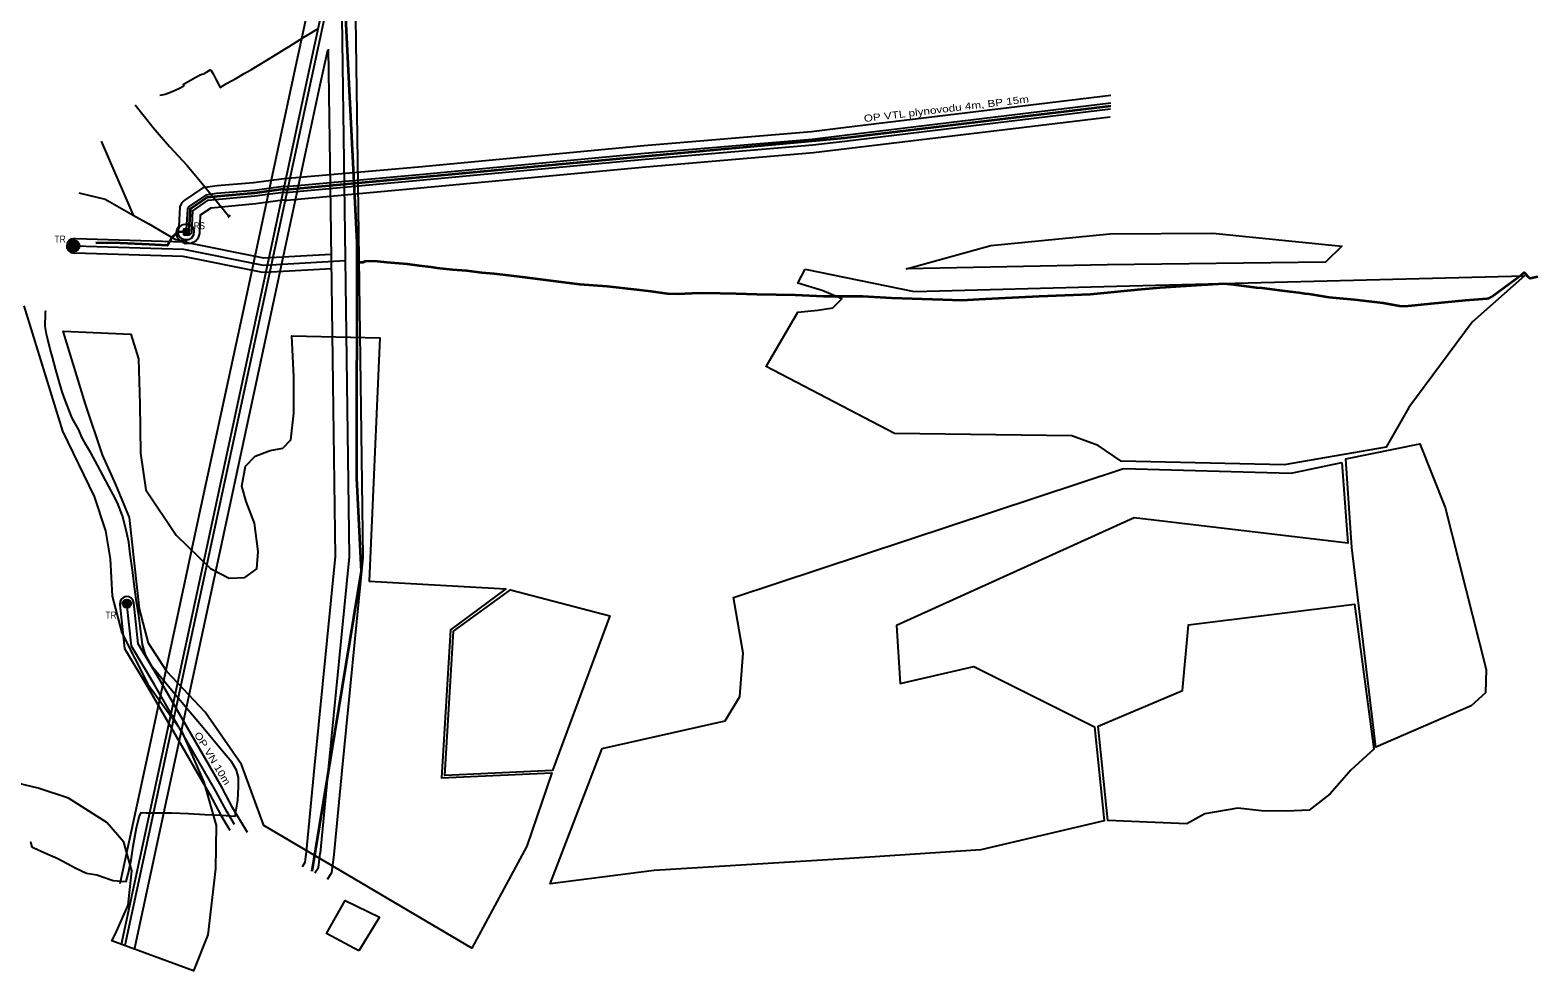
# Model space of a CAD drawing. Extents: x -589836 to -586543, y -1119607 to -1116793.
# Drawn here: x -588693 to -586543, y -1119607 to -1118266 of the extents above; entities that cross this region are included whole.
import ezdxf

# ---------------------------------------------------------------- set-up
doc = ezdxf.new("R2010")
doc.units = 0
doc.header["$LTSCALE"] = 4
for name, color, linetype, lineweight in [('21', 7, 'Continuous', 25), ('22', 7, 'Continuous', 25), ('25', 7, 'Continuous', 25), ('26', 7, 'Continuous', 25), ('29', 7, 'Continuous', 25), ('31', 7, 'Continuous', 25), ('45', 7, 'Continuous', 25), ('49', 7, 'Continuous', 25), ('51', 7, 'Continuous', 35), ('53', 7, 'Continuous', 35), ('57', 7, 'Continuous', 25), ('58', 7, 'Continuous', 25), ('59', 7, 'Continuous', 25)]:
    doc.layers.add(name, color=color, linetype=linetype, lineweight=lineweight)

msp = doc.modelspace()

# ---------------------------------------------------------------- hatches: boundary and pattern name
at = {"layer": '29'}
for points in [[(-588623.126, -1118573.346, 1), (-588639.226, -1118573.346, 1)], [(-588549.665, -1119083.315, 1), (-588561.739, -1119083.315, 1)]]:
    msp.add_hatch(color=256, dxfattribs=at).paths.add_polyline_path(points)
at = {"layer": '59'}
msp.add_hatch(color=256, dxfattribs=at).paths.add_polyline_path([(-588474.962, -1118557.448), (-588466.962, -1118557.448), (-588466.962, -1118549.448), (-588474.962, -1118549.448)])

# ---------------------------------------------------------------- linework, layer by layer
at = {"layer": '21'}
for points in [[(-587457.391, -1116891.203), (-587467.495, -1116906.128), (-587678.431, -1117217.658), (-587869.495, -1117499.964), (-588057.978, -1117778.27), (-588234.704, -1118039.283), (-588299.251, -1118339.426), (-588366.538, -1118652.377), (-588434.124, -1118966.627), (-588505.333, -1119297.805), (-588563.874, -1119569.266)], [(-588222.732, -1117991.024), (-588240.555, -1118139.541), (-588249.547, -1118212.86), (-588245.083, -1118520.625), (-588241.831, -1118769.889), (-588238.396, -1119016.784), (-588268.401, -1119319.835), (-588280.072, -1119439.07)], [(-588629.251, -1118573.381), (-588474.779, -1118578.006), (-588361.209, -1118600.912), (-588350.308, -1118600.364), (-588244.393, -1118594.251)], [(-588401.912, -1119398.276), (-588413.054, -1119379.796), (-588428.514, -1119350.663), (-588516.693, -1119198.167), (-588549.117, -1119143.934), (-588555.689, -1119083.288)], [(-588287.339, -1119467.122), (-588282.404, -1119459.508), (-588280.072, -1119439.07)]]:
    msp.add_lwpolyline(points, dxfattribs=at)
at = {"layer": '22'}
for points in [[(-588260.167, -1119441.018), (-588248.497, -1119321.794), (-588218.382, -1119017.633), (-588221.833, -1118769.619), (-588225.085, -1118520.35), (-588229.529, -1118213.937), (-588220.701, -1118141.95), (-588202.874, -1117993.407)], [(-588246.811, -1118021.492), (-588253.441, -1118031.284), (-588318.804, -1118335.221), (-588386.091, -1118648.172), (-588453.677, -1118962.422), (-588524.885, -1119293.595), (-588565.713, -1119482.918)], [(-588544.923, -1119576.263), (-588485.781, -1119302.015), (-588414.571, -1118970.832), (-588346.985, -1118656.582), (-588279.698, -1118343.631), (-588269.092, -1118294.315)], [(-588268.388, -1118292.891), (-588265.081, -1118520.9), (-588261.829, -1118770.159), (-588258.41, -1119015.935), (-588288.305, -1119317.876), (-588299.977, -1119437.122)], [(-588264.24, -1118585.38), (-588350.847, -1118590.378), (-588360.46, -1118590.862), (-588473.633, -1118568.036), (-588628.952, -1118563.385)], [(-588629.55, -1118583.377), (-588475.925, -1118587.976), (-588361.958, -1118610.962), (-588349.769, -1118610.35), (-588263.979, -1118605.398)], [(-588565.631, -1119084.365), (-588558.823, -1119147.187), (-588525.313, -1119203.236), (-588437.262, -1119355.511), (-588421.759, -1119384.725), (-588408.86, -1119406.12)], [(-588383.35, -1119409.696), (-588404.349, -1119374.867), (-588419.766, -1119345.815), (-588508.073, -1119193.098), (-588539.411, -1119140.681), (-588545.747, -1119082.211)], [(-588299.943, -1119436.803), (-588301.742, -1119452.573), (-588305.56, -1119458.464)], [(-588269.457, -1119476.304), (-588263.066, -1119466.443), (-588260.201, -1119441.337)]]:
    msp.add_lwpolyline(points, dxfattribs=at)
for centre, radius, start, end in [((-588631.176, -1118573.346), 10.206, 77.41396, 279.20742), ((-588555.689, -1119083.288), 10, 6.18264, 186.18264)]:
    msp.add_arc(centre, radius, start, end, dxfattribs=at)
at = {"layer": '25'}
msp.add_lwpolyline([(-587453.687, -1116893.154), (-588229.609, -1118041.457), (-588558.571, -1119570.952)], dxfattribs=at)
at = {"layer": '26'}
for points in [[(-588448.66, -1118328.38), (-588445.41, -1118327.83), (-588442.05, -1118325.59), (-588436.95, -1118322.56), (-588435.86, -1118323.02), (-588432.61, -1118327.98), (-588431.14, -1118330.67), (-588428.92, -1118335.66), (-588422.7, -1118347.43), (-588413.31, -1118341.77), (-588399.43, -1118333.99), (-588388.15, -1118327.5), (-588377.79, -1118321.88), (-588349.81, -1118304.9), (-588341.2, -1118299.4), (-588329.9, -1118292.46), (-588324.2, -1118289.02), (-588318.96, -1118285.98), (-588303.08, -1118275.73), (-588297.36, -1118272.24), (-588284.44, -1118264.16)], [(-588491.16, -1118353.17), (-588481.55, -1118348.82), (-588474.38, -1118345.04), (-588474.24, -1118344.52), (-588474.23, -1118344.19), (-588474.86, -1118342.87), (-588474.07, -1118342.27), (-588461.38, -1118335.31), (-588451.86, -1118329.92), (-588448.66, -1118328.38)], [(-588508.51, -1118358.49), (-588505.14, -1118358.08), (-588500.92, -1118356.95), (-588491.16, -1118353.17)], [(-588693.26, -1119423.62), (-588692.8, -1119423.53), (-588691.3, -1119430.3), (-588689.26, -1119431.22), (-588683.17, -1119433.96), (-588668.31, -1119440.47), (-588654.85, -1119446.03), (-588646.74, -1119450.41), (-588628.21, -1119460.68), (-588613.09, -1119467.49), (-588598.64, -1119470.05), (-588575, -1119478), (-588556.66, -1119479.54), (-588553.91, -1119469.06), (-588549.35, -1119449.22), (-588546.41, -1119429.3), (-588541.75, -1119402.8), (-588537.92, -1119387.07), (-588535.18, -1119381.34), (-588528.69, -1119381.52), (-588516.84, -1119381.44), (-588492.12, -1119381.56), (-588467.64, -1119382.47), (-588444.55, -1119383.85), (-588420.73, -1119384.88), (-588400.93, -1119386.31), (-588397.47, -1119363.42), (-588396.44, -1119344.44), (-588396.61, -1119331.22), (-588399.18, -1119320.84), (-588405.89, -1119309.42), (-588419.19, -1119293.72), (-588444.46, -1119263.25), (-588449.18, -1119257.64), (-588467.15, -1119236.1), (-588491.89, -1119206.56), (-588519.16, -1119173.98), (-588528.89, -1119156.11), (-588533.11, -1119141.77), (-588535.39, -1119126.68), (-588538.71, -1119100.28), (-588541.72, -1119080.76), (-588545.08, -1119055.45), (-588547.09, -1119039.14), (-588549.46, -1119022.37), (-588550.92, -1119013.06), (-588553, -1118995.85), (-588556.5, -1118978.44), (-588561.81, -1118958.38), (-588568.96, -1118939.87), (-588574.89, -1118927.96), (-588581.25, -1118916.23), (-588589.8, -1118900.37), (-588597.3, -1118886.03), (-588607.11, -1118868.2), (-588613.89, -1118856.25), (-588619.87, -1118846.11), (-588624.08, -1118835.53), (-588633.35, -1118818.97), (-588637.94, -1118808.18), (-588643.62, -1118793.34), (-588647.63, -1118781.51), (-588653.31, -1118763.48), (-588656.69, -1118750.17), (-588661.53, -1118732.2), (-588665.17, -1118720.57), (-588668.5, -1118706.99), (-588670.29, -1118699.03), (-588671.97, -1118687.72), (-588671.94, -1118682.03), (-588671.716, -1118675.944), (-588671.561, -1118671.707), (-588671.42, -1118667.88), (-588671.24, -1118666.44), (-588670.85, -1118666.42)]]:
    msp.add_lwpolyline(points, dxfattribs=at)
at = {"layer": '29'}
for centre, radius in [((-588631.176, -1118573.346), 8.05), ((-588555.702, -1119083.315), 6.037)]:
    msp.add_circle(centre, radius, dxfattribs=at)
at = {"layer": '31'}
for p, q in [((-588543.76, -1118372.1), (-588517.95, -1118404.41)), ((-588517.95, -1118404.41), (-588494.8, -1118431.51)), ((-588494.8, -1118431.51), (-588469.66, -1118458.68)), ((-588469.66, -1118458.68), (-588445.93, -1118487.06)), ((-588445.93, -1118487.06), (-588409.96, -1118530.99)), ((-588624.18, -1118497.82), (-588586.59, -1118506.54)), ((-588410.926, -1118531.781), (-588410.219, -1118532.646)), ((-588524.46, -1118542.09), (-588486.06, -1118564.06)), ((-588486.06, -1118564.06), (-588471.01, -1118566.77)), ((-588471.231, -1118568), (-588470.131, -1118568.198))]:
    msp.add_line(p, q, dxfattribs=at)
for points in [[(-588592.18, -1118424.23), (-588581.697, -1118448.396), (-588546.478, -1118529.471)], [(-588586.59, -1118506.54), (-588546.478, -1118529.471), (-588524.46, -1118542.09)], [(-588410.926, -1118531.781), (-588409.96, -1118530.99), (-588408.993, -1118530.198), (-588408.285, -1118531.063)], [(-588471.231, -1118568), (-588471.01, -1118566.77), (-588470.788, -1118565.541), (-588469.689, -1118565.739)]]:
    msp.add_lwpolyline(points, dxfattribs=at)
at = {"layer": '45'}
for points in [[(-587157.878, -1118600.13), (-587443.92, -1118606.155), (-587323.481, -1118572.59), (-587154.007, -1118556.238), (-587006.812, -1118555.143), (-586822.785, -1118573.611), (-586846.458, -1118596.688)], [(-587588.359, -1118606.576), (-587432.646, -1118638.42), (-587144.449, -1118630.674), (-586562.461, -1118616.043), (-586637.307, -1118682.313), (-586727.637, -1118803.663), (-586759.899, -1118860.466), (-586905.289, -1118885.425), (-587137.567, -1118880.261), (-587170.258, -1118857.884), (-587208.111, -1118844.114), (-587461.037, -1118840.671), (-587643.849, -1118745.14), (-587598.682, -1118667.682), (-587570.293, -1118665.1), (-587548.786, -1118661.657), (-587535.881, -1118648.748), (-587564.271, -1118636.699), (-587598.682, -1118626.371)], [(-588436.39, -1119033.042), (-588409.721, -1119046.812), (-588387.354, -1119045.952), (-588370.148, -1119033.903), (-588368.427, -1119008.944), (-588373.589, -1118968.494), (-588385.633, -1118937.511), (-588391.655, -1118915.995), (-588386.493, -1118887.594), (-588372.729, -1118872.963), (-588351.222, -1118865.217), (-588333.155, -1118861.774), (-588321.972, -1118849.725), (-588317.67, -1118811.857), (-588317.67, -1118760.219), (-588320.251, -1118701.695), (-588194.649, -1118704.277), (-588210.134, -1119051.116), (-588015.278, -1119062.303), (-588093.994, -1119120.826), (-588106.899, -1119331.684), (-587949.466, -1119324.798), (-587985.168, -1119428.936), (-588063.454, -1119574.386), (-588360.254, -1119399.675), (-588392.085, -1119312.751), (-588443.702, -1119237.875), (-588498.761, -1119180.212), (-588524.569, -1119139.762), (-588537.474, -1119090.705), (-588551.669, -1118960.748), (-588571.456, -1118913.413), (-588590.382, -1118871.241), (-588614.47, -1118798.948), (-588646.301, -1118694.81), (-588549.948, -1118699.113), (-588538.765, -1118734.399), (-588537.044, -1118798.948), (-588536.184, -1118868.66), (-588528.441, -1118921.159), (-588485.427, -1118985.707)], [(-586638.598, -1119228.823), (-586774.524, -1119288.207), (-586808.936, -1119003.335), (-586817.538, -1118876.82), (-586711.723, -1118855.304), (-586675.59, -1118946.532), (-586617.091, -1119177.184), (-586617.951, -1119210.75)], [(-586823.13, -1118881.984), (-586814.527, -1118997.31), (-587119.07, -1118961.163), (-587458.025, -1119114.357), (-587452.863, -1119196.979), (-587347.908, -1119172.881), (-587175.85, -1119258.945), (-587162.085, -1119393.206), (-587337.584, -1119434.517), (-587525.128, -1119446.566), (-587803.862, -1119463.779), (-587951.832, -1119482.713), (-587877.847, -1119289.929), (-587702.348, -1119250.339), (-587681.701, -1119215.913), (-587676.539, -1119153.947), (-587690.304, -1119074.768), (-587134.556, -1118890.59), (-586895.395, -1118897.475)], [(-587948.605, -1119321.34), (-588102.167, -1119328.225), (-588089.693, -1119122.532), (-588008.611, -1119063.578), (-587866.663, -1119100.585)], [(-586839.477, -1119354.478), (-586869.587, -1119377.715), (-586901.418, -1119379.436), (-586937.55, -1119378.576), (-586971.101, -1119375.133), (-587018.417, -1119382.879), (-587044.226, -1119397.51), (-587156.924, -1119392.346), (-587170.689, -1119258.086), (-587050.248, -1119207.308), (-587041.645, -1119113.497), (-586805.065, -1119084.236), (-586777.536, -1119290.79), (-586810.227, -1119320.912)], [(-588224.581, -1119578.45), (-588270.713, -1119553.598), (-588244.098, -1119506.556), (-588195.305, -1119530.521)]]:
    msp.add_lwpolyline(points, close=True, dxfattribs=at)
msp.add_lwpolyline([(-588702.65, -1118658.663), (-588647.591, -1118837.676), (-588601.996, -1118930.626), (-588586.08, -1118979.682), (-588579.198, -1119019.271), (-588576.617, -1119072.631), (-588562.852, -1119125.13), (-588525.86, -1119198.285), (-588477.684, -1119264.554), (-588445.853, -1119337.709), (-588428.218, -1119399.675), (-588429.078, -1119461.642), (-588440.262, -1119555.452), (-588460.564, -1119606.853), (-588576.781, -1119564.249), (-588572.101, -1119555.023), (-588553.605, -1119513.282), (-588548.443, -1119464.226), (-588560.057, -1119423.345), (-588584.145, -1119395.374), (-588638.774, -1119360.518), (-588682.003, -1119346.317), (-588734.05, -1119333.837)], dxfattribs=at)
at = {"layer": '49', "lineweight": 35}
for points in [[(-588441.71, -1117474.54), (-588446.09, -1117528.74), (-588444.76, -1117558.39), (-588437.14, -1117857.91), (-588248.114, -1118205.264), (-588244.69, -1118228.95), (-588227.86, -1118568.33), (-588227.89, -1118904.6), (-588221.46, -1119036.99), (-588291.911, -1119465.134)], [(-588227.862, -1118596.071), (-588227.17, -1118596.1), (-588225.633, -1118596.541), (-588218.842, -1118596.704), (-588215.757, -1118595.207), (-588208.32, -1118594.76), (-588198.22, -1118595.31), (-588184.89, -1118596.77), (-588155.79, -1118598.77), (-588138.53, -1118601.37), (-588121.9, -1118603), (-588113.59, -1118604.7), (-588091.35, -1118607), (-588071.14, -1118608.31), (-588049.7, -1118611.12), (-588031.79, -1118612.69), (-588011.43, -1118614.99), (-587991.9, -1118617.51), (-587951.4, -1118622.46), (-587910.06, -1118627.69), (-587870.67, -1118630.88), (-587828.33, -1118635.46), (-587808.43, -1118637.82), (-587785.11, -1118641.34), (-587769.44, -1118641.7), (-587740.24, -1118640.48), (-587709.69, -1118640.77), (-587686.61, -1118641.27), (-587657.24, -1118642.03), (-587629.57, -1118642.62), (-587602.65, -1118643.23), (-587562.07, -1118645.05), (-587506.2, -1118645.09), (-587465.26, -1118647.38), (-587391.76, -1118649.67), (-587364.88, -1118650.57), (-587340.26, -1118649.36), (-587312.63, -1118647.95), (-587254.52, -1118645.04), (-587181.23, -1118642.04), (-587138.31, -1118637.89), (-587113.78, -1118635.48), (-587082.201, -1118632.602), (-587030.24, -1118629.35), (-586991.35, -1118626.91), (-586977.11, -1118628.6), (-586945.18, -1118632.59), (-586937.32, -1118633.19), (-586905, -1118637.53), (-586884.15, -1118640.02), (-586875.7, -1118641.18), (-586869.93, -1118641.7), (-586841.36, -1118646.29), (-586804.92, -1118649.93), (-586784.53, -1118652.09), (-586764.15, -1118654.75), (-586740.9, -1118659.02), (-586733.36, -1118659.43), (-586695.61, -1118655.52), (-586646.75, -1118650.93), (-586615.65, -1118648.39), (-586612.85, -1118647.97), (-586609.37, -1118646.06), (-586566.23, -1118614.16), (-586562.78, -1118611.1), (-586556.15, -1118618.23), (-586554.777, -1118619.565), (-586554.24, -1118619.48), (-586543.491, -1118617.115)]]:
    msp.add_lwpolyline(points, dxfattribs=at)
at = {"layer": '51'}
msp.add_lwpolyline([(-587152.644, -1118374.006), (-587531.92, -1118419.94), (-587816.95, -1118445.75), (-588138.13, -1118475.85), (-588328.75, -1118493.41), (-588332.76, -1118492.63), (-588373.3, -1118498.14), (-588426.89, -1118502.7), (-588441.24, -1118504.36), (-588465.17, -1118521.14), (-588467.12, -1118550.43), (-588467.13, -1118553.49), (-588469.47, -1118553.86)], dxfattribs=at)
at = {"layer": '53', "lineweight": 25}
for p, q in [((-588476.352, -1118553.485), (-588476.65, -1118553.49)), ((-588476.06, -1118553.48), (-588476.352, -1118553.485)), ((-588467.12, -1118550.43), (-588467.12, -1118550.92))]:
    msp.add_line(p, q, dxfattribs=at)
at = {"layer": '53'}
msp.add_line((-588476.06, -1118553.48), (-588476.352, -1118553.485), dxfattribs=at)
for points in [[(-588482.84, -1118553.6), (-588490.8, -1118561.01), (-588497.62, -1118572.94), (-588523.68, -1118571.14), (-588565.27, -1118569.64), (-588599.803, -1118568.754)], [(-588476.352, -1118553.485), (-588476.65, -1118553.49), (-588482.84, -1118553.6)], [(-588472.67, -1118553.47), (-588475.41, -1118553.47), (-588476.06, -1118553.48)]]:
    msp.add_lwpolyline(points, dxfattribs=at)
at = {"layer": '57'}
msp.add_lwpolyline([(-587152.39, -1118358.865), (-587533.65, -1118405.04), (-587579.28, -1118410.526), (-587818.284, -1118430.809), (-588139.518, -1118460.914), (-588331.103, -1118477.671), (-588374.947, -1118483.226), (-588426.666, -1118487.627), (-588447.465, -1118490.681), (-588473.782, -1118508.859), (-588477.655, -1118512.382), (-588479.936, -1118517.802), (-588481.646, -1118545.471), (-588484.212, -1118550.035), (-588485.068, -1118554.599), (-588483.642, -1118561.445), (-588479.365, -1118565.439), (-588472.237, -1118570.003), (-588464.254, -1118569.432), (-588457.412, -1118566.295), (-588453.42, -1118561.16), (-588451.424, -1118555.74), (-588450.569, -1118529.212), (-588435.173, -1118518.943), (-588371.653, -1118513.054), (-588333.193, -1118507.827), (-588328.436, -1118508.445), (-588327.374, -1118508.347), (-588136.742, -1118490.786), (-587815.616, -1118460.691), (-587576.22, -1118440.374), (-587153.302, -1118389.185)], dxfattribs=at)
at = {"layer": '58'}
msp.add_lwpolyline([(-587152.586, -1118369.969), (-587532.381, -1118415.967), (-587578.158, -1118421.47), (-587817.306, -1118441.766), (-588138.5, -1118471.867), (-588328.548, -1118489.374), (-588332.644, -1118488.578), (-588373.739, -1118494.163), (-588427.68, -1118498.702), (-588443.132, -1118500.801), (-588467.467, -1118517.865), (-588469.161, -1118520.874), (-588471.112, -1118550.174), (-588472.899, -1118551.298), (-588473.68, -1118553.955), (-588472.431, -1118556.767), (-588469.151, -1118557.861), (-588465.715, -1118557.236), (-588463.216, -1118555.205), (-588462.748, -1118553.642), (-588461.306, -1118523.316), (-588439.766, -1118508.212), (-588372.861, -1118502.117), (-588332.876, -1118496.682), (-588328.952, -1118497.446), (-588137.76, -1118479.833), (-587816.594, -1118449.734), (-587577.342, -1118429.43), (-587531.82, -1118423.954), (-587152.702, -1118378.041)], dxfattribs=at)
msp.add_lwpolyline([(-588475.663, -1118543.118), (-588477.466, -1118543.88), (-588480.464, -1118546.369), (-588482.368, -1118549.734), (-588482.497, -1118553.581), (-588482.497, -1118557.171), (-588479.805, -1118561.274), (-588478.011, -1118562.557), (-588474.935, -1118563.967), (-588471.218, -1118564.352), (-588467.501, -1118564.223), (-588463.016, -1118561.915), (-588460.068, -1118557.043), (-588459.683, -1118552.683), (-588460.068, -1118549.093), (-588461.478, -1118546.272), (-588464.297, -1118544.092), (-588468.27, -1118542.681), (-588472.768, -1118542.71)], close=True, dxfattribs=at)
at = {"layer": '59'}
msp.add_lwpolyline([(-588474.962, -1118557.448), (-588466.962, -1118557.448), (-588466.962, -1118549.448), (-588474.962, -1118549.448)], close=True, dxfattribs=at)

# ---------------------------------------------------------------- texts
at = {"layer": '22', "width": 1.2}
msp.add_text('OP VN 10m', height=10, rotation=301.254, dxfattribs=at).set_placement((-588459.978, -1119269.924))
at = {"layer": '29', "width": 0.9}
for p in [(-588658.774, -1118568.623), (-588586.256, -1119104.596)]:
    msp.add_text('TR', height=10, dxfattribs=at).set_placement(p)
at = {"layer": '57', "width": 1.25}
msp.add_text('OP VTL plynovodu 4m, BP 15m', height=10, rotation=6.809, dxfattribs=at).set_placement((-587504, -1118396.81))
at = {"layer": '59', "width": 0.85}
msp.add_text('RS', height=10, dxfattribs=at).set_placement((-588460.077, -1118549.554))

doc.saveas('drawing.dxf')
